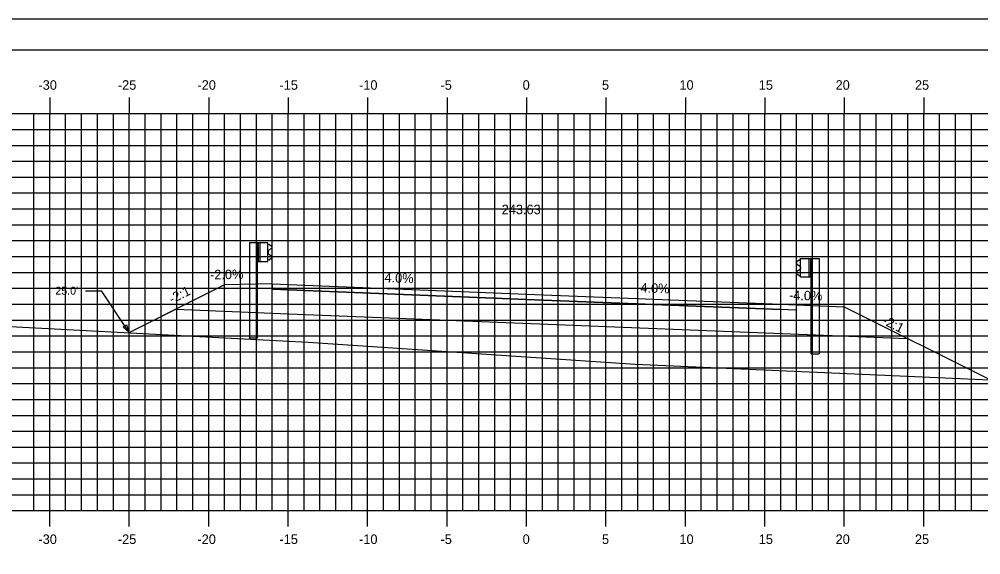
# Model space of a CAD drawing. Extents: x 1160718 to 1173142, y 616002 to 617630.
# Drawn here: x 1168156.4 to 1168216.9, y 616690.1 to 616723.9 of the extents above; entities that cross this region are included whole.
import ezdxf

# ---------------------------------------------------------------- set-up
doc = ezdxf.new("R2010")
doc.units = 0
for name, color, linetype in [('ANNOTATION', 7, 'Continuous'), ('BORDER', 7, 'Continuous'), ('D_Guardrail_Beam_Lt', 7, 'Continuous'), ('D_Guardrail_Beam_Rt', 7, 'Continuous'), ('D_Roadway_Centerline', 7, 'Continuous'), ('D_Roadway_Centerline_Text', 7, 'Continuous'), ('D_Roadway_Edge_Shoulder', 7, 'Continuous'), ('D_Roadway_Edge_TW', 7, 'Continuous'), ('D_Roadway_Pavement', 7, 'Continuous'), ('D_Roadway_SlopeLines', 7, 'Continuous'), ('D_Roadway_SubGrade', 7, 'Continuous'), ('H_V ANNOTATION', 7, 'Continuous'), ('MAJOR', 7, 'Continuous'), ('MINOR', 7, 'Continuous'), ('PLOT BOUNDARY', 7, 'Continuous'), ('S_Roadway_Centerline', 7, 'Continuous'), ('SHADING', 7, 'Continuous')]:
    doc.layers.add(name, color=color, linetype=linetype)

msp = doc.modelspace()

# ---------------------------------------------------------------- linework, layer by layer
at = {"layer": 'ANNOTATION'}
for p, q in [((1168160.593, 616706.777), (1168161.593, 616706.777)), ((1168163.342, 616704.14), (1168161.593, 616706.777)), ((1168204.342, 616705.92), (1168208.338, 616705.76))]:
    msp.add_line(p, q, dxfattribs=at)
msp.add_lwpolyline([(1168163.169, 616704.625), (1168163.342, 616704.14), (1168162.961, 616704.487)], close=True, dxfattribs=at)
at = {"layer": 'BORDER'}
msp.add_line((1168273.342, 616721.928), (1168113.342, 616721.928), dxfattribs=at)
at = {"layer": 'D_Guardrail_Beam_Lt'}
for p, q in [((1168170.914, 616709.783), (1168170.914, 616703.783)), ((1168171.385, 616709.783), (1168170.914, 616709.783)), ((1168172.072, 616709.783), (1168171.385, 616709.783)), ((1168171.385, 616709.783), (1168171.385, 616708.616)), ((1168171.447, 616709.783), (1168171.447, 616708.616)), ((1168171.552, 616709.783), (1168171.552, 616708.616)), ((1168172.072, 616708.616), (1168172.072, 616709.783)), ((1168172.072, 616709.699), (1168172.147, 616709.685)), ((1168172.162, 616709.678), (1168172.306, 616709.578)), ((1168172.077, 616709.235), (1168172.077, 616709.164)), ((1168172.306, 616709.435), (1168172.11, 616709.299)), ((1168172.11, 616709.1), (1168172.306, 616708.964)), ((1168171.385, 616708.616), (1168172.072, 616708.616)), ((1168171.406, 616703.783), (1168171.406, 616708.616)), ((1168172.147, 616708.714), (1168172.072, 616708.699)), ((1168172.306, 616708.821), (1168172.162, 616708.721)), ((1168171.406, 616703.783), (1168170.914, 616703.783))]:
    msp.add_line(p, q, dxfattribs=at)
for centre, major_axis, start_param, end_param in [((1168172.138, 616709.644), (0.0417, 0), 0.959931, 1.376053), ((1168172.256, 616709.507), (0.0877, 0), 5.323254, 7.243116), ((1168172.156, 616709.235), (-0.0789, 0), 5.323254, 6.283185), ((1168172.156, 616709.164), (-0.0789, 0), 6.283185, 7.243116), ((1168172.256, 616708.892), (0.0877, 0), 5.323254, 7.243116), ((1168172.138, 616708.755), (0.0417, 0), 4.907132, 5.323254)]:
    msp.add_ellipse(centre, major_axis=major_axis, ratio=0.995501, start_param=start_param, end_param=end_param, dxfattribs=at)
at = {"layer": 'D_Guardrail_Beam_Rt'}
for p, q in [((1168205.505, 616708.694), (1168205.361, 616708.594)), ((1168205.361, 616708.451), (1168205.557, 616708.315)), ((1168205.595, 616708.716), (1168205.521, 616708.701)), ((1168205.595, 616708.799), (1168206.282, 616708.799)), ((1168205.595, 616707.632), (1168205.595, 616708.799)), ((1168206.116, 616708.799), (1168206.116, 616707.632)), ((1168206.22, 616708.799), (1168206.22, 616707.632)), ((1168206.282, 616708.799), (1168206.753, 616708.799)), ((1168206.282, 616708.799), (1168206.282, 616707.632)), ((1168206.753, 616708.799), (1168206.753, 616702.799)), ((1168205.557, 616708.116), (1168205.361, 616707.98)), ((1168205.361, 616707.837), (1168205.505, 616707.737)), ((1168205.521, 616707.73), (1168205.595, 616707.716)), ((1168205.59, 616708.251), (1168205.59, 616708.18)), ((1168206.282, 616707.632), (1168205.595, 616707.632)), ((1168206.261, 616702.799), (1168206.261, 616707.632)), ((1168206.261, 616702.799), (1168206.753, 616702.799))]:
    msp.add_line(p, q, dxfattribs=at)
for centre, major_axis, start_param, end_param in [((1168205.412, 616708.523), (-0.0877, 0), 5.323254, 7.243116), ((1168205.529, 616708.66), (-0.0417, 0), 4.907132, 5.323254), ((1168205.412, 616707.908), (-0.0877, 0), 5.323254, 7.243116), ((1168205.529, 616707.771), (-0.0417, 0), 0.959931, 1.376053), ((1168205.511, 616708.251), (0.0789, 0), 0, 0.959931), ((1168205.511, 616708.18), (0.0789, 0), 5.323254, 6.283185)]:
    msp.add_ellipse(centre, major_axis=major_axis, ratio=0.995501, start_param=start_param, end_param=end_param, dxfattribs=at)
at = {"layer": 'D_Roadway_Edge_Shoulder'}
msp.add_lwpolyline([(1168172.342, 616707.2), (1168172.342, 616706.866)], dxfattribs=at)
at = {"layer": 'D_Roadway_Edge_TW'}
for p, q in [((1168172.342, 616706.866), (1168172.342, 616707.2)), ((1168172.342, 616707.2), (1168188.342, 616706.56)), ((1168188.342, 616706.226), (1168172.342, 616706.866)), ((1168188.342, 616706.56), (1168204.342, 616705.92)), ((1168205.328, 616705.547), (1168188.342, 616706.226))]:
    msp.add_line(p, q, dxfattribs=at)
at = {"layer": 'D_Roadway_Pavement'}
msp.add_lwpolyline([(1168172.342, 616706.866), (1168172.342, 616706.866), (1168188.342, 616706.226), (1168204.342, 616705.586), (1168204.342, 616705.586), (1168188.342, 616706.226)], close=True, dxfattribs=at)
for points in [[(1168172.342, 616706.866), (1168172.342, 616706.866)], [(1168172.342, 616706.866), (1168172.342, 616706.866)], [(1168204.342, 616705.586), (1168204.342, 616705.586)], [(1168204.342, 616705.586), (1168204.342, 616705.586)]]:
    msp.add_lwpolyline(points, dxfattribs=at)
at = {"layer": 'D_Roadway_SlopeLines'}
for points in [[(1168169.342, 616707.14), (1168163.31, 616704.124)], [(1168208.342, 616705.76), (1168217.545, 616701.158)]]:
    msp.add_lwpolyline(points, dxfattribs=at)
at = {"layer": 'D_Roadway_SubGrade'}
for p, q in [((1168169.342, 616707.14), (1168165.354, 616705.146)), ((1168172.342, 616707.2), (1168169.342, 616707.14)), ((1168172.342, 616705.366), (1168172.342, 616707.2)), ((1168172.342, 616705.366), (1168172.342, 616706.866)), ((1168172.342, 616706.866), (1168188.342, 616706.226)), ((1168188.342, 616706.226), (1168204.342, 616705.586)), ((1168205.342, 616704.046), (1168205.342, 616705.88))]:
    msp.add_line(p, q, dxfattribs=at)
at = {"layer": 'MAJOR'}
for p, q in [((1168158.342, 616718.93), (1168158.342, 616717.928)), ((1168163.342, 616718.93), (1168163.342, 616717.928)), ((1168168.342, 616718.93), (1168168.342, 616717.928)), ((1168173.342, 616718.93), (1168173.342, 616717.928)), ((1168178.342, 616718.93), (1168178.342, 616717.928)), ((1168183.342, 616718.93), (1168183.342, 616717.928)), ((1168188.342, 616718.93), (1168188.342, 616717.928)), ((1168193.342, 616718.93), (1168193.342, 616717.928)), ((1168198.342, 616718.93), (1168198.342, 616717.928)), ((1168203.342, 616718.93), (1168203.342, 616717.928)), ((1168208.342, 616718.93), (1168208.342, 616717.928)), ((1168213.342, 616718.93), (1168213.342, 616717.928)), ((1168118.342, 616717.928), (1168258.342, 616717.928)), ((1168118.342, 616717.928), (1168258.342, 616717.928)), ((1168158.342, 616692.928), (1168158.342, 616717.928)), ((1168163.342, 616692.928), (1168163.342, 616717.928)), ((1168168.342, 616692.928), (1168168.342, 616717.928)), ((1168173.342, 616692.928), (1168173.342, 616717.928)), ((1168178.342, 616692.928), (1168178.342, 616717.928)), ((1168183.342, 616692.928), (1168183.342, 616717.928)), ((1168188.342, 616692.928), (1168188.342, 616717.928)), ((1168193.342, 616692.928), (1168193.342, 616717.928)), ((1168198.342, 616692.928), (1168198.342, 616717.928)), ((1168203.342, 616692.928), (1168203.342, 616717.928)), ((1168208.342, 616692.928), (1168208.342, 616717.928)), ((1168213.342, 616692.928), (1168213.342, 616717.928)), ((1168118.342, 616712.928), (1168258.342, 616712.928)), ((1168118.342, 616707.928), (1168258.342, 616707.928)), ((1168118.342, 616702.928), (1168258.342, 616702.928)), ((1168118.342, 616697.928), (1168258.342, 616697.928)), ((1168118.342, 616692.928), (1168258.342, 616692.928)), ((1168118.342, 616692.928), (1168258.342, 616692.928)), ((1168158.342, 616691.926), (1168158.342, 616692.928)), ((1168163.342, 616691.926), (1168163.342, 616692.928)), ((1168168.342, 616691.926), (1168168.342, 616692.928)), ((1168173.342, 616691.926), (1168173.342, 616692.928)), ((1168178.342, 616691.926), (1168178.342, 616692.928)), ((1168183.342, 616691.926), (1168183.342, 616692.928)), ((1168188.342, 616691.926), (1168188.342, 616692.928)), ((1168193.342, 616691.926), (1168193.342, 616692.928)), ((1168198.342, 616691.926), (1168198.342, 616692.928)), ((1168203.342, 616691.926), (1168203.342, 616692.928)), ((1168208.342, 616691.926), (1168208.342, 616692.928)), ((1168213.342, 616691.926), (1168213.342, 616692.928))]:
    msp.add_line(p, q, dxfattribs=at)
at = {"layer": 'MINOR'}
for p, q in [((1168157.342, 616692.928), (1168157.342, 616717.928)), ((1168159.342, 616692.928), (1168159.342, 616717.928)), ((1168160.342, 616692.928), (1168160.342, 616717.928)), ((1168161.342, 616692.928), (1168161.342, 616717.928)), ((1168162.342, 616692.928), (1168162.342, 616717.928)), ((1168164.342, 616692.928), (1168164.342, 616717.928)), ((1168165.342, 616692.928), (1168165.342, 616717.928)), ((1168166.342, 616692.928), (1168166.342, 616717.928)), ((1168167.342, 616692.928), (1168167.342, 616717.928)), ((1168169.342, 616692.928), (1168169.342, 616717.928)), ((1168170.342, 616692.928), (1168170.342, 616717.928)), ((1168171.342, 616692.928), (1168171.342, 616717.928)), ((1168172.342, 616692.928), (1168172.342, 616717.928)), ((1168174.342, 616692.928), (1168174.342, 616717.928)), ((1168175.342, 616692.928), (1168175.342, 616717.928)), ((1168176.342, 616692.928), (1168176.342, 616717.928)), ((1168177.342, 616692.928), (1168177.342, 616717.928)), ((1168179.342, 616692.928), (1168179.342, 616717.928)), ((1168180.342, 616692.928), (1168180.342, 616717.928)), ((1168181.342, 616692.928), (1168181.342, 616717.928)), ((1168182.342, 616692.928), (1168182.342, 616717.928)), ((1168184.342, 616692.928), (1168184.342, 616717.928)), ((1168185.342, 616692.928), (1168185.342, 616717.928)), ((1168186.342, 616692.928), (1168186.342, 616717.928)), ((1168187.342, 616692.928), (1168187.342, 616717.928)), ((1168189.342, 616692.928), (1168189.342, 616717.928)), ((1168190.342, 616692.928), (1168190.342, 616717.928)), ((1168191.342, 616692.928), (1168191.342, 616717.928)), ((1168192.342, 616692.928), (1168192.342, 616717.928)), ((1168194.342, 616692.928), (1168194.342, 616717.928)), ((1168195.342, 616692.928), (1168195.342, 616717.928)), ((1168196.342, 616692.928), (1168196.342, 616717.928)), ((1168197.342, 616692.928), (1168197.342, 616717.928)), ((1168199.342, 616692.928), (1168199.342, 616717.928)), ((1168200.342, 616692.928), (1168200.342, 616717.928)), ((1168201.342, 616692.928), (1168201.342, 616717.928)), ((1168202.342, 616692.928), (1168202.342, 616717.928)), ((1168204.342, 616692.928), (1168204.342, 616717.928)), ((1168205.342, 616692.928), (1168205.342, 616717.928)), ((1168206.342, 616692.928), (1168206.342, 616717.928)), ((1168207.342, 616692.928), (1168207.342, 616717.928)), ((1168209.342, 616692.928), (1168209.342, 616717.928)), ((1168210.342, 616692.928), (1168210.342, 616717.928)), ((1168211.342, 616692.928), (1168211.342, 616717.928)), ((1168212.342, 616692.928), (1168212.342, 616717.928)), ((1168214.342, 616692.928), (1168214.342, 616717.928)), ((1168215.342, 616692.928), (1168215.342, 616717.928)), ((1168216.342, 616692.928), (1168216.342, 616717.928)), ((1168118.342, 616716.928), (1168258.342, 616716.928)), ((1168118.342, 616715.928), (1168258.342, 616715.928)), ((1168118.342, 616714.928), (1168258.342, 616714.928)), ((1168118.342, 616713.928), (1168258.342, 616713.928)), ((1168118.342, 616711.928), (1168258.342, 616711.928)), ((1168118.342, 616710.928), (1168258.342, 616710.928)), ((1168118.342, 616709.928), (1168258.342, 616709.928)), ((1168118.342, 616708.928), (1168258.342, 616708.928)), ((1168118.342, 616706.928), (1168258.342, 616706.928)), ((1168118.342, 616705.928), (1168258.342, 616705.928)), ((1168118.342, 616704.928), (1168258.342, 616704.928)), ((1168118.342, 616703.928), (1168258.342, 616703.928)), ((1168118.342, 616701.928), (1168258.342, 616701.928)), ((1168118.342, 616700.928), (1168258.342, 616700.928)), ((1168118.342, 616699.928), (1168258.342, 616699.928)), ((1168118.342, 616698.928), (1168258.342, 616698.928)), ((1168118.342, 616696.928), (1168258.342, 616696.928)), ((1168118.342, 616695.928), (1168258.342, 616695.928)), ((1168118.342, 616694.928), (1168258.342, 616694.928)), ((1168118.342, 616693.928), (1168258.342, 616693.928))]:
    msp.add_line(p, q, dxfattribs=at)
at = {"layer": 'PLOT BOUNDARY'}
msp.add_lwpolyline([(1168105.248, 616613.869), (1168275.248, 616613.869), (1168275.248, 616723.869), (1168105.248, 616723.869)], close=True, dxfattribs=at)
at = {"layer": 'S_Roadway_Centerline'}
msp.add_lwpolyline([(1168118.342, 616706.742), (1168118.445, 616706.733), (1168141.796, 616705.469), (1168150.433, 616704.829), (1168152.24, 616704.705), (1168171.383, 616703.699), (1168174.599, 616703.54), (1168195.177, 616702.14), (1168209.955, 616701.5), (1168217.511, 616701.159)], dxfattribs=at)
at = {"layer": 'SHADING'}
msp.add_lwpolyline([(1168166.28, 616705.609), (1168172.342, 616705.366), (1168212.327, 616703.767)], dxfattribs=at)

# ---------------------------------------------------------------- texts
at = {"layer": 'ANNOTATION'}
for s, rotation, p in [('-2.0%', 1.14576, (1168168.434, 616707.48)), ('4.0%', 357.70939, (1168179.398, 616707.318)), ('-4.0%', 357.70939, (1168195.237, 616706.685)), ('-2:1', 26.56505, (1168166.021, 616705.944)), ('-4.0%', 358.85424, (1168204.857, 616706.195)), ('-2:1', 333.43495, (1168210.676, 616704.71))]:
    msp.add_text(s, height=0.6, rotation=rotation, dxfattribs=at).set_placement(p)
msp.add_text("25.0'", height=0.5, dxfattribs=at).set_placement((1168158.693, 616706.527))
at = {"layer": 'D_Roadway_Centerline'}
for s, p in [('C', (1168188.336, 616706.56)), ('L', (1168188.342, 616706.552))]:
    msp.add_text(s, height=0.0146, dxfattribs=at).set_placement(p)
at = {"layer": 'D_Roadway_Centerline_Text'}
msp.add_text('243.63', height=0.6, dxfattribs=at).set_placement((1168186.782, 616711.592))
at = {"layer": 'H_V ANNOTATION'}
for s, p in [('-30', (1168157.63, 616719.428)), ('-25', (1168162.627, 616719.428)), ('-20', (1168167.635, 616719.428)), ('-15', (1168172.798, 616719.428)), ('-10', (1168177.806, 616719.428)), ('-5', (1168182.932, 616719.428)), ('0', (1168188.101, 616719.428)), ('5', (1168193.093, 616719.428)), ('10', (1168197.967, 616719.428)), ('15', (1168202.959, 616719.428)), ('20', (1168207.796, 616719.428)), ('25', (1168212.788, 616719.428)), ('-30', (1168157.63, 616690.828)), ('-25', (1168162.627, 616690.828)), ('-20', (1168167.635, 616690.828)), ('-15', (1168172.798, 616690.828)), ('-10', (1168177.806, 616690.828)), ('-5', (1168182.932, 616690.828)), ('0', (1168188.101, 616690.828)), ('5', (1168193.093, 616690.828)), ('10', (1168197.967, 616690.828)), ('15', (1168202.959, 616690.828)), ('20', (1168207.796, 616690.828)), ('25', (1168212.788, 616690.828))]:
    msp.add_text(s, height=0.6, dxfattribs=at).set_placement(p)

doc.saveas('drawing.dxf')
